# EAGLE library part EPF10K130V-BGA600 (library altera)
EPF10K130 FLEX 10K family
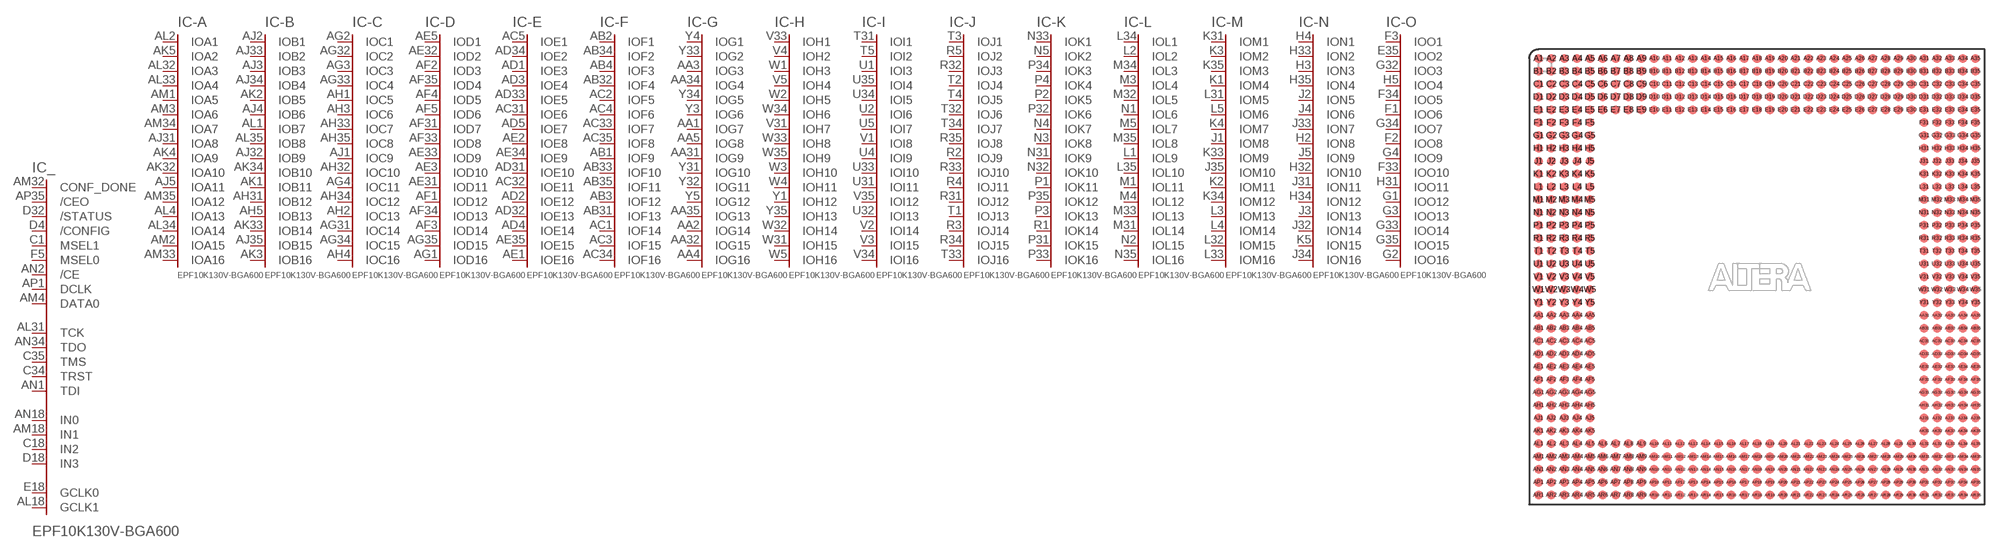
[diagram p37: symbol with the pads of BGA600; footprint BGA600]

Designator prefix IC; gates _=130V600C -A=A16 -B=B16 -C=C16 -D=D16 -E=E16 -F=F16 -G=G16 -H=H16 -I=I16 -J=J16 -K=K16 -L=L16 -M=M16 -N=N16 -O=O16 -P=P16 -1=IO44 -2=IO84 -3=IO124 -4=IO164 -5=IO204 -6=IO244 -7=IO284 -8=IO324 -9=IO364 -10=IO404 -11=IO444 -12=IO484 -13=IO524 G1=GND G2=GND G3=GND G4=GND G5=GND G6=GND G7=GND G8=GND G9=GND G10=GND G11=GND G12=GND G13=GND G14=GND G15=GND G16=GND G17=GND G18=GND G19=GND G20=GND G21=GND G22=GND G23=GND G24=GND G25=GND G26=GND G27=GND G28=GND G29=GND G30=GND G31=GND G32=GND G33=GND G34=GND G35=GND G36=GND G37=GND G38=GND G39=GND G40=GND G41=GND G42=GND G43=GND G44=GND G45=GND G46=GND G47=GND G48=GND G49=GND G50=GND G51=GND G52=GND G53=GND G54=GND G55=GND G56=GND G57=GND G58=GND V1=VCCINT V2=VCCINT V3=VCCINT V4=VCCINT V5=VCCINT V6=VCCINT V7=VCCINT V8=VCCINT V9=VCCINT V10=VCCINT V11=VCCINT V12=VCCINT V13=VCCINT V14=VCCINT V15=VCCINT V16=VCCINT V17=VCCINT V18=VCCINT V19=VCCINT V20=VCCINT V21=VCCINT V22=VCCINT V23=VCCINT V24=VCCINT V25=VCCINT V26=VCCINT V27=VCCINT V28=VCCINT V29=VCCINT V30=VCCIO V31=VCCIO V32=VCCIO V33=VCCIO V34=VCCIO V35=VCCIO V36=VCCIO V37=VCCIO V38=VCCIO V39=VCCIO V40=VCCIO V41=VCCIO V42=VCCIO V43=VCCIO V44=VCCIO V45=VCCIO V46=VCCIO V47=VCCIO V48=VCCIO V49=VCCIO V50=VCCIO V51=VCCIO V52=VCCIO V53=VCCIO V54=VCCIO V55=VCCIO V56=VCCIO V57=VCCIO V58=VCCIO

## EPF10K130V-BGA600 (OC_FARNELL: unknown; OC_NEWARK: unknown)  [BGA600]
A1  G30:GND  pwr
A2  G31:GND  pwr
A3  G32:GND  pwr
A4  G33:GND  pwr
A5  G34:GND  pwr
A6  -1:IO14
A7  -1:IO34
A8  -2:IO54
A9  -2:IO81
A10  -3:IO101
A11  V13:VCC  pwr
A12  -4:IO144
A13  -5:IO174
A14  -5:IO191
A15  -6:IO214
A16  -6:IO243
A17  -7:IO261
A18  G35:GND  pwr
A19  V14:VCC  pwr
A20  V44:VCCIO  pwr
A21  -8:IO314
A22  -9:IO334
A23  -9:IO363
A24  -10:IO384
A25  -10:IO393
A26  -11:IO424
A27  V45:VCCIO  pwr
A28  -12:IO474
A29  -13:IO493
A30  -13:IO523
A31  G36:GND  pwr
A32  G37:GND  pwr
A33  G38:GND  pwr
A34  G39:GND  pwr
A35  G40:GND  pwr
AA1  -G:IOG7
AA2  -G:IOG14
AA3  -G:IOG3
AA4  -G:IOG16
AA5  -G:IOG8
AA31  -G:IOG9
AA32  -G:IOG15
AA33  V1:VCC  pwr
AA34  -G:IOG4
AA35  -G:IOG13
AB1  -F:IOF9
AB2  -F:IOF1
AB3  -F:IOF12
AB4  -F:IOF3
AB5  V2:VCC  pwr
AB31  -F:IOF13
AB32  -F:IOF4
AB33  -F:IOF10
AB34  -F:IOF2
AB35  -F:IOF11
AC1  -F:IOF14
AC2  -F:IOF5
AC3  -F:IOF15
AC4  -F:IOF6
AC5  -E:IOE1
AC31  -E:IOE6
AC32  -E:IOE11
AC33  -F:IOF7
AC34  -F:IOF16
AC35  -F:IOF8
AD1  -E:IOE3
AD2  -E:IOE12
AD3  -E:IOE4
AD4  -E:IOE14
AD5  -E:IOE7
AD31  -E:IOE10
AD32  -E:IOE13
AD33  -E:IOE5
AD34  -E:IOE2
AD35  V3:VCC  pwr
AE1  -E:IOE16
AE2  -E:IOE8
AE3  -D:IOD10
AE4  V4:VCC  pwr
AE5  -D:IOD1
AE31  -D:IOD11
AE32  -D:IOD2
AE33  -D:IOD9
AE34  -E:IOE9
AE35  -E:IOE15
AF1  -D:IOD12
AF2  -D:IOD3
AF3  -D:IOD14
AF4  -D:IOD5
AF5  -D:IOD6
AF31  -D:IOD7
AF32  V5:VCC  pwr
AF33  -D:IOD8
AF34  -D:IOD13
AF35  -D:IOD4
AG1  -D:IOD16
AG2  -C:IOC1
AG3  -C:IOC3
AG4  -C:IOC11
AG5  V6:VCC  pwr
AG31  -C:IOC14
AG32  -C:IOC2
AG33  -C:IOC4
AG34  -C:IOC15
AG35  -D:IOD15
AH1  -C:IOC5
AH2  -C:IOC13
AH3  -C:IOC6
AH4  -C:IOC16
AH5  -B:IOB13
AH31  -B:IOB12
AH32  -C:IOC10
AH33  -C:IOC7
AH34  -C:IOC12
AH35  -C:IOC8
AJ1  -C:IOC9
AJ2  -B:IOB1
AJ3  -B:IOB3
AJ4  -B:IOB6
AJ5  -A:IOA11
AJ31  -A:IOA8
AJ32  -B:IOB9
AJ33  -B:IOB2
AJ34  -B:IOB4
AJ35  -B:IOB15
AK1  -B:IOB11
AK2  -B:IOB5
AK3  -B:IOB16
AK4  -A:IOA9
AK5  -A:IOA2
AK31  V7:VCC  pwr
AK32  -A:IOA10
AK33  -B:IOB14
AK34  -B:IOB10
AK35  V8:VCC  pwr
AL1  -B:IOB7
AL2  -A:IOA1
AL3  V9:VCC  pwr
AL4  -A:IOA13
AL5  V30:VCCIO  pwr
AL6  G1:GND  pwr
AL7  -1:IO12
AL8  -1:IO41
AL9  -2:IO62
AL10  -2:IO82
AL11  -3:IO112
AL12  V31:VCCIO  pwr
AL13  -4:IO152
AL14  -5:IO172
AL15  -5:IO201
AL16  -6:IO222
AL17  -6:IO241
AL18  _:GCLK1  in
AL19  -8:IO291
AL20  -8:IO312
AL21  -9:IO342
AL22  -9:IO361
AL23  -10:IO383
AL24  -11:IO412
AL25  -11:IO433
AL26  -12:IO451
AL27  -12:IO473
AL28  -13:IO502
AL29  -13:IO521
AL30  G2:GND  pwr
AL31  _:TCK
AL32  -A:IOA3
AL33  -A:IOA4
AL34  -A:IOA14
AL35  -B:IOB8
AM1  -A:IOA5
AM2  -A:IOA15
AM3  -A:IOA6
AM4  _:DATA0  in
AM5  V32:VCCIO  pwr
AM6  G3:GND  pwr
AM7  -1:IO21
AM8  -1:IO42
AM9  -2:IO61
AM10  -3:IO91
AM11  -3:IO113
AM12  -4:IO133
AM13  -4:IO151
AM14  -5:IO181
AM15  -5:IO202
AM16  -6:IO221
AM17  -7:IO252
AM18  _:IN1  in
AM19  V33:VCCIO  pwr
AM20  -8:IO311
AM21  -9:IO331
AM22  -9:IO362
AM23  -10:IO382
AM24  -10:IO402
AM25  -11:IO421
AM26  V34:VCCIO  pwr
AM27  -12:IO472
AM28  -13:IO491
AM29  -13:IO522
AM30  G4:GND  pwr
AM31  V35:VCCIO  pwr
AM32  _:CONF_DONE  in
AM33  -A:IOA16
AM34  -A:IOA7
AM35  -A:IOA12
AN1  _:TDI
AN2  _:/CE  in
AN3  V36:VCCIO  pwr
AN4  V37:VCCIO  pwr
AN5  G5:GND  pwr
AN6  G6:GND  pwr
AN7  -1:IO22
AN8  V38:VCCIO  pwr
AN9  -2:IO72
AN10  -3:IO92
AN11  -3:IO121
AN12  -4:IO132
AN13  -4:IO163
AN14  -5:IO182
AN15  V39:VCCIO  pwr
AN16  -6:IO233
AN17  -7:IO251
AN18  _:IN0  in
AN19  -7:IO283
AN20  -8:IO303
AN21  -9:IO332
AN22  -9:IO352
AN23  -10:IO372
AN24  -10:IO392
AN25  -11:IO422
AN26  -11:IO441
AN27  -12:IO462
AN28  -13:IO492
AN29  -13:IO511
AN30  G7:GND  pwr
AN31  G8:GND  pwr
AN32  V40:VCCIO  pwr
AN33  V41:VCCIO  pwr
AN34  _:TDO
AN35  G9:GND  pwr
AP1  _:DCLK  in
AP2  G10:GND  pwr
AP3  G11:GND  pwr
AP4  G12:GND  pwr
AP5  G13:GND  pwr
AP6  G14:GND  pwr
AP7  -1:IO31
AP8  -2:IO53
AP9  -2:IO71
AP10  -3:IO102
AP11  -3:IO122
AP12  -4:IO142
AP13  -4:IO162
AP14  -5:IO192
AP15  -6:IO213
AP16  -6:IO232
AP17  -7:IO262
AP18  -7:IO272
AP19  -7:IO282
AP20  -8:IO302
AP21  -8:IO323
AP22  -9:IO353
AP23  -10:IO371
AP24  V10:VCC  pwr
AP25  -11:IO413
AP26  -11:IO442
AP27  -12:IO461
AP28  -12:IO482
AP29  -13:IO512
AP30  G15:GND  pwr
AP31  G16:GND  pwr
AP32  G17:GND  pwr
AP33  G18:GND  pwr
AP34  V42:VCCIO  pwr
AP35  _:/CEO  in
AR1  G19:GND  pwr
AR2  G20:GND  pwr
AR3  G21:GND  pwr
AR4  G22:GND  pwr
AR5  G23:GND  pwr
AR6  -1:IO11
AR7  -1:IO32
AR8  -2:IO52
AR9  -2:IO83
AR10  -3:IO103
AR11  V11:VCC  pwr
AR12  -4:IO141
AR13  -5:IO171
AR14  -5:IO193
AR15  -6:IO212
AR16  -6:IO242
AR17  -7:IO263
AR18  V12:VCC  pwr
AR19  -7:IO271
AR20  -8:IO292
AR21  -8:IO322
AR22  -9:IO341
AR23  V43:VCCIO  pwr
AR24  -10:IO391
AR25  -10:IO403
AR26  -11:IO432
AR27  -12:IO452
AR28  -12:IO481
AR29  -13:IO501
AR30  G24:GND  pwr
AR31  G25:GND  pwr
AR32  G26:GND  pwr
AR33  G27:GND  pwr
AR34  G28:GND  pwr
AR35  G29:GND  pwr
B1  V15:VCC  pwr
B2  G41:GND  pwr
B3  G42:GND  pwr
B4  G43:GND  pwr
B5  G44:GND  pwr
B6  G45:GND  pwr
B7  -1:IO33
B8  -2:IO51
B9  -2:IO74
B10  -3:IO104
B11  -3:IO123
B12  -4:IO143
B13  -4:IO164
B14  -5:IO194
B15  -6:IO211
B16  -6:IO234
B17  -7:IO264
B18  V16:VCC  pwr
B19  -7:IO273
B20  -8:IO294
B21  -8:IO313
B22  -9:IO343
B23  -9:IO364
B24  -10:IO381
B25  -10:IO404
B26  -11:IO431
B27  -12:IO453
B28  -12:IO471
B29  -13:IO503
B30  -13:IO524
B31  G46:GND  pwr
B32  G47:GND  pwr
B33  G48:GND  pwr
B34  G49:GND  pwr
B35  G50:GND  pwr
C1  _:MSEL1  in
C2  V46:VCCIO  pwr
C3  V47:VCCIO  pwr
C4  V48:VCCIO  pwr
C5  G51:GND  pwr
C6  G52:GND  pwr
C7  -1:IO23
C8  V49:VCCIO  pwr
C9  -2:IO73
C10  -3:IO93
C11  -3:IO124
C12  -4:IO134
C13  -4:IO161
C14  -5:IO183
C15  V50:VCCIO  pwr
C16  -6:IO231
C17  -7:IO253
C18  _:IN2  in
C19  -7:IO274
C20  -8:IO293
C21  -8:IO324
C22  -9:IO344
C23  V51:VCCIO  pwr
C24  -10:IO394
C25  -11:IO411
C26  -11:IO434
C27  -12:IO454
C28  -12:IO484
C29  -13:IO504
C30  G53:GND  pwr
C31  G54:GND  pwr
C32  V52:VCCIO  pwr
C33  V53:VCCIO  pwr
C34  _:TRST
C35  _:TMS
D1  -P:IOP9
D2  -P:IOP5
D3  -P:IOP10
D4  _:/CONFIG  in
D5  V54:VCCIO  pwr
D6  G55:GND  pwr
D7  -1:IO24
D8  -1:IO43
D9  -2:IO64
D10  -3:IO94
D11  -3:IO111
D12  -4:IO131
D13  -4:IO154
D14  -5:IO184
D15  -5:IO203
D16  -6:IO224
D17  -7:IO254
D18  _:IN3  in
D19  -7:IO281
D20  -8:IO304
D21  -8:IO321
D22  -9:IO351
D23  -10:IO374
D24  V17:VCC  pwr
D25  -11:IO414
D26  -11:IO443
D27  -12:IO464
D28  -12:IO483
D29  -13:IO513
D30  G56:GND  pwr
D31  V55:VCCIO  pwr
D32  _:/STATUS  in
D33  -P:IOP13
D34  -P:IOP3
D35  -P:IOP11
E1  -P:IOP15
E2  V18:VCC  pwr
E3  -P:IOP8
E4  -P:IOP1
E5  V56:VCCIO  pwr
E6  G57:GND  pwr
E7  -1:IO13
E8  -1:IO44
E9  -2:IO63
E10  -2:IO84
E11  -3:IO114
E12  V57:VCCIO  pwr
E13  -4:IO153
E14  -5:IO173
E15  -5:IO204
E16  -6:IO223
E17  -6:IO244
E18  _:GCLK0  in
E19  -7:IO284
E20  -8:IO301
E21  -9:IO333
E22  -9:IO354
E23  -10:IO373
E24  -10:IO401
E25  -11:IO423
E26  -11:IO444
E27  -12:IO463
E28  -13:IO494
E29  -13:IO514
E30  G58:GND  pwr
E31  V58:VCCIO  pwr
E32  -P:IOP2
E33  -P:IOP7
E34  -P:IOP16
E35  -O:IOO2
F1  -O:IOO6
F2  -O:IOO8
F3  -O:IOO1
F4  -P:IOP12
F5  _:MSEL0  in
F31  V19:VCC  pwr
F32  -P:IOP14
F33  -O:IOO10
F34  -O:IOO5
F35  V20:VCC  pwr
G1  -O:IOO12
G2  -O:IOO16
G3  -O:IOO13
G4  -O:IOO9
G5  -P:IOP4
G31  -P:IOP6
G32  -O:IOO3
G33  -O:IOO14
G34  -O:IOO7
G35  -O:IOO15
H1  V21:VCC  pwr
H2  -N:ION8
H3  -N:ION3
H4  -N:ION1
H5  -O:IOO4
H31  -O:IOO11
H32  -N:ION10
H33  -N:ION2
H34  -N:ION12
H35  -N:ION4
J1  -M:IOM8
J2  -N:ION5
J3  -N:ION13
J4  -N:ION6
J5  -N:ION9
J31  -N:ION11
J32  -N:ION14
J33  -N:ION7
J34  -N:ION16
J35  -M:IOM10
K1  -M:IOM4
K2  -M:IOM11
K3  -M:IOM2
K4  -M:IOM7
K5  -N:ION15
K31  -M:IOM1
K32  V22:VCC  pwr
K33  -M:IOM9
K34  -M:IOM12
K35  -M:IOM3
L1  -L:IOL9
L2  -L:IOL2
L3  -M:IOM13
L4  -M:IOM14
L5  -M:IOM6
L31  -M:IOM5
L32  -M:IOM15
L33  -M:IOM16
L34  -L:IOL1
L35  -L:IOL10
M1  -L:IOL11
M2  V23:VCC  pwr
M3  -L:IOL4
M4  -L:IOL12
M5  -L:IOL7
M31  -L:IOL14
M32  -L:IOL5
M33  -L:IOL13
M34  -L:IOL3
M35  -L:IOL8
N1  -L:IOL6
N2  -L:IOL15
N3  -K:IOK8
N4  -K:IOK7
N5  -K:IOK2
N31  -K:IOK9
N32  -K:IOK10
N33  -K:IOK1
N34  V24:VCC  pwr
N35  -L:IOL16
P1  -K:IOK11
P2  -K:IOK5
P3  -K:IOK13
P4  -K:IOK4
P5  V25:VCC  pwr
P31  -K:IOK15
P32  -K:IOK6
P33  -K:IOK16
P34  -K:IOK3
P35  -K:IOK12
R1  -K:IOK14
R2  -J:IOJ9
R3  -J:IOJ14
R4  -J:IOJ11
R5  -J:IOJ2
R31  -J:IOJ12
R32  -J:IOJ3
R33  -J:IOJ10
R34  -J:IOJ15
R35  -J:IOJ8
T1  -J:IOJ13
T2  -J:IOJ4
T3  -J:IOJ1
T4  -J:IOJ5
T5  -I:IOI2
T31  -I:IOI1
T32  -J:IOJ6
T33  -J:IOJ16
T34  -J:IOJ7
T35  V26:VCC  pwr
U1  -I:IOI3
U2  -I:IOI6
U3  V27:VCC  pwr
U4  -I:IOI9
U5  -I:IOI7
U31  -I:IOI11
U32  -I:IOI13
U33  -I:IOI10
U34  -I:IOI5
U35  -I:IOI4
V1  -I:IOI8
V2  -I:IOI14
V3  -I:IOI15
V4  -H:IOH2
V5  -H:IOH4
V31  -H:IOH7
V32  V28:VCC  pwr
V33  -H:IOH1
V34  -I:IOI16
V35  -I:IOI12
W1  -H:IOH3
W2  -H:IOH5
W3  -H:IOH10
W4  -H:IOH11
W5  -H:IOH16
W31  -H:IOH15
W32  -H:IOH14
W33  -H:IOH8
W34  -H:IOH6
W35  -H:IOH9
Y1  -H:IOH12
Y2  V29:VCC  pwr
Y3  -G:IOG6
Y4  -G:IOG1
Y5  -G:IOG12
Y31  -G:IOG10
Y32  -G:IOG11
Y33  -G:IOG2
Y34  -G:IOG5
Y35  -H:IOH13

## Footprint BGA600 (pad centres in mm)
Ball Grid Array
smd 0.9 x 0.9: A1 -21.59,21.59; A2 -20.32,21.59; A3 -19.05,21.59; A4 -17.78,21.59; A5 -16.51,21.59; A6 -15.24,21.59; A7 -13.97,21.59; A8 -12.7,21.59; A9 -11.43,21.59; A10 -10.16,21.59; A11 -8.89,21.59; A12 -7.62,21.59; A13 -6.35,21.59; A14 -5.08,21.59; A15 -3.81,21.59; A16 -2.54,21.59; A17 -1.27,21.59; A18 0,21.59; A19 1.27,21.59; A20 2.54,21.59; A21 3.81,21.59; A22 5.08,21.59; A23 6.35,21.59; A24 7.62,21.59; A25 8.89,21.59; A26 10.16,21.59; A27 11.43,21.59; A28 12.7,21.59; A29 13.97,21.59; A30 15.24,21.59; A31 16.51,21.59; A32 17.78,21.59; A33 19.05,21.59; A34 20.32,21.59; A35 21.59,21.59; AA1 -21.59,-3.81; AA2 -20.32,-3.81; AA3 -19.05,-3.81; AA4 -17.78,-3.81; AA5 -16.51,-3.81; AA31 16.51,-3.81; AA32 17.78,-3.81; AA33 19.05,-3.81; AA34 20.32,-3.81; AA35 21.59,-3.81; AB1 -21.59,-5.08; AB2 -20.32,-5.08; AB3 -19.05,-5.08; AB4 -17.78,-5.08; AB5 -16.51,-5.08; AB31 16.51,-5.08; AB32 17.78,-5.08; AB33 19.05,-5.08; AB34 20.32,-5.08; AB35 21.59,-5.08; AC1 -21.59,-6.35; AC2 -20.32,-6.35; AC3 -19.05,-6.35; AC4 -17.78,-6.35; AC5 -16.51,-6.35; AC31 16.51,-6.35; AC32 17.78,-6.35; AC33 19.05,-6.35; AC34 20.32,-6.35; AC35 21.59,-6.35; AD1 -21.59,-7.62; AD2 -20.32,-7.62; AD3 -19.05,-7.62; AD4 -17.78,-7.62; AD5 -16.51,-7.62; AD31 16.51,-7.62; AD32 17.78,-7.62; AD33 19.05,-7.62; AD34 20.32,-7.62; AD35 21.59,-7.62; AE1 -21.59,-8.89; AE2 -20.32,-8.89; AE3 -19.05,-8.89; AE4 -17.78,-8.89; AE5 -16.51,-8.89; AE31 16.51,-8.89; AE32 17.78,-8.89; AE33 19.05,-8.89; AE34 20.32,-8.89; AE35 21.59,-8.89; AF1 -21.59,-10.16; AF2 -20.32,-10.16; AF3 -19.05,-10.16; AF4 -17.78,-10.16; AF5 -16.51,-10.16; AF31 16.51,-10.16; AF32 17.78,-10.16; AF33 19.05,-10.16; AF34 20.32,-10.16; AF35 21.59,-10.16; AG1 -21.59,-11.43; AG2 -20.32,-11.43; AG3 -19.05,-11.43; AG4 -17.78,-11.43; AG5 -16.51,-11.43; AG31 16.51,-11.43; AG32 17.78,-11.43; AG33 19.05,-11.43; AG34 20.32,-11.43; AG35 21.59,-11.43; AH1 -21.59,-12.7; AH2 -20.32,-12.7; AH3 -19.05,-12.7; AH4 -17.78,-12.7; AH5 -16.51,-12.7; AH31 16.51,-12.7; AH32 17.78,-12.7; AH33 19.05,-12.7; AH34 20.32,-12.7; AH35 21.59,-12.7; AJ1 -21.59,-13.97; AJ2 -20.32,-13.97; AJ3 -19.05,-13.97; AJ4 -17.78,-13.97; AJ5 -16.51,-13.97; AJ31 16.51,-13.97; AJ32 17.78,-13.97; AJ33 19.05,-13.97; AJ34 20.32,-13.97; AJ35 21.59,-13.97; AK1 -21.59,-15.24; AK2 -20.32,-15.24; AK3 -19.05,-15.24; AK4 -17.78,-15.24; AK5 -16.51,-15.24; AK31 16.51,-15.24; AK32 17.78,-15.24; AK33 19.05,-15.24; AK34 20.32,-15.24; AK35 21.59,-15.24; AL1 -21.59,-16.51; AL2 -20.32,-16.51; AL3 -19.05,-16.51; AL4 -17.78,-16.51; AL5 -16.51,-16.51; AL6 -15.24,-16.51; AL7 -13.97,-16.51; AL8 -12.7,-16.51; AL9 -11.43,-16.51; AL10 -10.16,-16.51; AL11 -8.89,-16.51; AL12 -7.62,-16.51; AL13 -6.35,-16.51; AL14 -5.08,-16.51; AL15 -3.81,-16.51; AL16 -2.54,-16.51; AL17 -1.27,-16.51; AL18 0,-16.51; AL19 1.27,-16.51; AL20 2.54,-16.51; AL21 3.81,-16.51; AL22 5.08,-16.51; AL23 6.35,-16.51; AL24 7.62,-16.51; AL25 8.89,-16.51; AL26 10.16,-16.51; AL27 11.43,-16.51; AL28 12.7,-16.51; AL29 13.97,-16.51; AL30 15.24,-16.51; AL31 16.51,-16.51; AL32 17.78,-16.51; AL33 19.05,-16.51; AL34 20.32,-16.51; AL35 21.59,-16.51; AM1 -21.59,-17.78; AM2 -20.32,-17.78; AM3 -19.05,-17.78; AM4 -17.78,-17.78; AM5 -16.51,-17.78; AM6 -15.24,-17.78; AM7 -13.97,-17.78; AM8 -12.7,-17.78; AM9 -11.43,-17.78; AM10 -10.16,-17.78; AM11 -8.89,-17.78; AM12 -7.62,-17.78; AM13 -6.35,-17.78; AM14 -5.08,-17.78; AM15 -3.81,-17.78; AM16 -2.54,-17.78; AM17 -1.27,-17.78; AM18 0,-17.78; AM19 1.27,-17.78; AM20 2.54,-17.78; AM21 3.81,-17.78; AM22 5.08,-17.78; AM23 6.35,-17.78; AM24 7.62,-17.78; AM25 8.89,-17.78; AM26 10.16,-17.78; AM27 11.43,-17.78; AM28 12.7,-17.78; AM29 13.97,-17.78; AM30 15.24,-17.78; AM31 16.51,-17.78; AM32 17.78,-17.78; AM33 19.05,-17.78; AM34 20.32,-17.78; AM35 21.59,-17.78; AN1 -21.59,-19.05; AN2 -20.32,-19.05; AN3 -19.05,-19.05; AN4 -17.78,-19.05; AN5 -16.51,-19.05; AN6 -15.24,-19.05; AN7 -13.97,-19.05; AN8 -12.7,-19.05; AN9 -11.43,-19.05; AN10 -10.16,-19.05; AN11 -8.89,-19.05; AN12 -7.62,-19.05; AN13 -6.35,-19.05; AN14 -5.08,-19.05; AN15 -3.81,-19.05; AN16 -2.54,-19.05; AN17 -1.27,-19.05; AN18 0,-19.05; AN19 1.27,-19.05; AN20 2.54,-19.05; AN21 3.81,-19.05; AN22 5.08,-19.05; AN23 6.35,-19.05; AN24 7.62,-19.05; AN25 8.89,-19.05; AN26 10.16,-19.05; AN27 11.43,-19.05; AN28 12.7,-19.05; AN29 13.97,-19.05; AN30 15.24,-19.05; AN31 16.51,-19.05; AN32 17.78,-19.05; AN33 19.05,-19.05; AN34 20.32,-19.05; AN35 21.59,-19.05; AP1 -21.59,-20.32; AP2 -20.32,-20.32; AP3 -19.05,-20.32; AP4 -17.78,-20.32; AP5 -16.51,-20.32; AP6 -15.24,-20.32; AP7 -13.97,-20.32; AP8 -12.7,-20.32; AP9 -11.43,-20.32; AP10 -10.16,-20.32; AP11 -8.89,-20.32; AP12 -7.62,-20.32; AP13 -6.35,-20.32; AP14 -5.08,-20.32; AP15 -3.81,-20.32; AP16 -2.54,-20.32; AP17 -1.27,-20.32; AP18 0,-20.32; AP19 1.27,-20.32; AP20 2.54,-20.32; AP21 3.81,-20.32; AP22 5.08,-20.32; AP23 6.35,-20.32; AP24 7.62,-20.32; AP25 8.89,-20.32; AP26 10.16,-20.32; AP27 11.43,-20.32; AP28 12.7,-20.32; AP29 13.97,-20.32; AP30 15.24,-20.32; AP31 16.51,-20.32; AP32 17.78,-20.32; AP33 19.05,-20.32; AP34 20.32,-20.32; AP35 21.59,-20.32; AR1 -21.59,-21.59; AR2 -20.32,-21.59; AR3 -19.05,-21.59; AR4 -17.78,-21.59; AR5 -16.51,-21.59; AR6 -15.24,-21.59; AR7 -13.97,-21.59; AR8 -12.7,-21.59; AR9 -11.43,-21.59; AR10 -10.16,-21.59; AR11 -8.89,-21.59; AR12 -7.62,-21.59; AR13 -6.35,-21.59; AR14 -5.08,-21.59; AR15 -3.81,-21.59; AR16 -2.54,-21.59; AR17 -1.27,-21.59; AR18 0,-21.59; AR19 1.27,-21.59; AR20 2.54,-21.59; AR21 3.81,-21.59; AR22 5.08,-21.59; AR23 6.35,-21.59; AR24 7.62,-21.59; AR25 8.89,-21.59; AR26 10.16,-21.59; AR27 11.43,-21.59; AR28 12.7,-21.59; AR29 13.97,-21.59; AR30 15.24,-21.59; AR31 16.51,-21.59; AR32 17.78,-21.59; AR33 19.05,-21.59; AR34 20.32,-21.59; AR35 21.59,-21.59; B1 -21.59,20.32; B2 -20.32,20.32; B3 -19.05,20.32; B4 -17.78,20.32; B5 -16.51,20.32; B6 -15.24,20.32; B7 -13.97,20.32; B8 -12.7,20.32; B9 -11.43,20.32; B10 -10.16,20.32; B11 -8.89,20.32; B12 -7.62,20.32; B13 -6.35,20.32; B14 -5.08,20.32; B15 -3.81,20.32; B16 -2.54,20.32; B17 -1.27,20.32; B18 0,20.32; B19 1.27,20.32; B20 2.54,20.32; B21 3.81,20.32; B22 5.08,20.32; B23 6.35,20.32; B24 7.62,20.32; B25 8.89,20.32; B26 10.16,20.32; B27 11.43,20.32; B28 12.7,20.32; B29 13.97,20.32; B30 15.24,20.32; B31 16.51,20.32; B32 17.78,20.32; B33 19.05,20.32; B34 20.32,20.32; B35 21.59,20.32; C1 -21.59,19.05; C2 -20.32,19.05; C3 -19.05,19.05; C4 -17.78,19.05; C5 -16.51,19.05; C6 -15.24,19.05; C7 -13.97,19.05; C8 -12.7,19.05; C9 -11.43,19.05; C10 -10.16,19.05; C11 -8.89,19.05; C12 -7.62,19.05; C13 -6.35,19.05; C14 -5.08,19.05; C15 -3.81,19.05; C16 -2.54,19.05; C17 -1.27,19.05; C18 0,19.05; C19 1.27,19.05; C20 2.54,19.05; C21 3.81,19.05; C22 5.08,19.05; C23 6.35,19.05; C24 7.62,19.05; C25 8.89,19.05; C26 10.16,19.05; C27 11.43,19.05; C28 12.7,19.05; C29 13.97,19.05; C30 15.24,19.05; C31 16.51,19.05; C32 17.78,19.05; C33 19.05,19.05; C34 20.32,19.05; C35 21.59,19.05; D1 -21.59,17.78; D2 -20.32,17.78; D3 -19.05,17.78; D4 -17.78,17.78; D5 -16.51,17.78; D6 -15.24,17.78; D7 -13.97,17.78; D8 -12.7,17.78; D9 -11.43,17.78; D10 -10.16,17.78; D11 -8.89,17.78; D12 -7.62,17.78; D13 -6.35,17.78; D14 -5.08,17.78; D15 -3.81,17.78; D16 -2.54,17.78; D17 -1.27,17.78; D18 0,17.78; D19 1.27,17.78; D20 2.54,17.78; D21 3.81,17.78; D22 5.08,17.78; D23 6.35,17.78; D24 7.62,17.78; D25 8.89,17.78; D26 10.16,17.78; D27 11.43,17.78; D28 12.7,17.78; D29 13.97,17.78; D30 15.24,17.78; D31 16.51,17.78; D32 17.78,17.78; D33 19.05,17.78; D34 20.32,17.78; D35 21.59,17.78; E1 -21.59,16.51; E2 -20.32,16.51; E3 -19.05,16.51; E4 -17.78,16.51; E5 -16.51,16.51; E6 -15.24,16.51; E7 -13.97,16.51; E8 -12.7,16.51; E9 -11.43,16.51; E10 -10.16,16.51; E11 -8.89,16.51; E12 -7.62,16.51; E13 -6.35,16.51; E14 -5.08,16.51; E15 -3.81,16.51; E16 -2.54,16.51; E17 -1.27,16.51; E18 0,16.51; E19 1.27,16.51; E20 2.54,16.51; E21 3.81,16.51; E22 5.08,16.51; E23 6.35,16.51; E24 7.62,16.51; E25 8.89,16.51; E26 10.16,16.51; E27 11.43,16.51; E28 12.7,16.51; E29 13.97,16.51; E30 15.24,16.51; E31 16.51,16.51; E32 17.78,16.51; E33 19.05,16.51; E34 20.32,16.51; E35 21.59,16.51; F1 -21.59,15.24; F2 -20.32,15.24; F3 -19.05,15.24; F4 -17.78,15.24; F5 -16.51,15.24; F31 16.51,15.24; F32 17.78,15.24; F33 19.05,15.24; F34 20.32,15.24; F35 21.59,15.24; G1 -21.59,13.97; G2 -20.32,13.97; G3 -19.05,13.97; G4 -17.78,13.97; G5 -16.51,13.97; G31 16.51,13.97; G32 17.78,13.97; G33 19.05,13.97; G34 20.32,13.97; G35 21.59,13.97; H1 -21.59,12.7; H2 -20.32,12.7; H3 -19.05,12.7; H4 -17.78,12.7; H5 -16.51,12.7; H31 16.51,12.7; H32 17.78,12.7; H33 19.05,12.7; H34 20.32,12.7; H35 21.59,12.7; J1 -21.59,11.43; J2 -20.32,11.43; J3 -19.05,11.43; J4 -17.78,11.43; J5 -16.51,11.43; J31 16.51,11.43; J32 17.78,11.43; J33 19.05,11.43; J34 20.32,11.43; J35 21.59,11.43; K1 -21.59,10.16; K2 -20.32,10.16; K3 -19.05,10.16; K4 -17.78,10.16; K5 -16.51,10.16; K31 16.51,10.16; K32 17.78,10.16; K33 19.05,10.16; K34 20.32,10.16; K35 21.59,10.16; L1 -21.59,8.89; L2 -20.32,8.89; L3 -19.05,8.89; L4 -17.78,8.89; L5 -16.51,8.89; L31 16.51,8.89; L32 17.78,8.89; L33 19.05,8.89; L34 20.32,8.89; L35 21.59,8.89; M1 -21.59,7.62; M2 -20.32,7.62; M3 -19.05,7.62; M4 -17.78,7.62; M5 -16.51,7.62; M31 16.51,7.62; M32 17.78,7.62; M33 19.05,7.62; M34 20.32,7.62; M35 21.59,7.62; N1 -21.59,6.35; N2 -20.32,6.35; N3 -19.05,6.35; N4 -17.78,6.35; N5 -16.51,6.35; N31 16.51,6.35; N32 17.78,6.35; N33 19.05,6.35; N34 20.32,6.35; N35 21.59,6.35; P1 -21.59,5.08; P2 -20.32,5.08; P3 -19.05,5.08; P4 -17.78,5.08; P5 -16.51,5.08; P31 16.51,5.08; P32 17.78,5.08; P33 19.05,5.08; P34 20.32,5.08; P35 21.59,5.08; R1 -21.59,3.81; R2 -20.32,3.81; R3 -19.05,3.81; R4 -17.78,3.81; R5 -16.51,3.81; R31 16.51,3.81; R32 17.78,3.81; R33 19.05,3.81; R34 20.32,3.81; R35 21.59,3.81; T1 -21.59,2.54; T2 -20.32,2.54; T3 -19.05,2.54; T4 -17.78,2.54; T5 -16.51,2.54; T31 16.51,2.54; T32 17.78,2.54; T33 19.05,2.54; T34 20.32,2.54; T35 21.59,2.54; U1 -21.59,1.27; U2 -20.32,1.27; U3 -19.05,1.27; U4 -17.78,1.27; U5 -16.51,1.27; U31 16.51,1.27; U32 17.78,1.27; U33 19.05,1.27; U34 20.32,1.27; U35 21.59,1.27; V1 -21.59,0; V2 -20.32,0; V3 -19.05,0; V4 -17.78,0; V5 -16.51,0; V31 16.51,0; V32 17.78,0; V33 19.05,0; V34 20.32,0; V35 21.59,0; W1 -21.59,-1.27; W2 -20.32,-1.27; W3 -19.05,-1.27; W4 -17.78,-1.27; W5 -16.51,-1.27; W31 16.51,-1.27; W32 17.78,-1.27; W33 19.05,-1.27; W34 20.32,-1.27; W35 21.59,-1.27; Y1 -21.59,-2.54; Y2 -20.32,-2.54; Y3 -19.05,-2.54; Y4 -17.78,-2.54; Y5 -16.51,-2.54; Y31 16.51,-2.54; Y32 17.78,-2.54; Y33 19.05,-2.54; Y34 20.32,-2.54; Y35 21.59,-2.54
